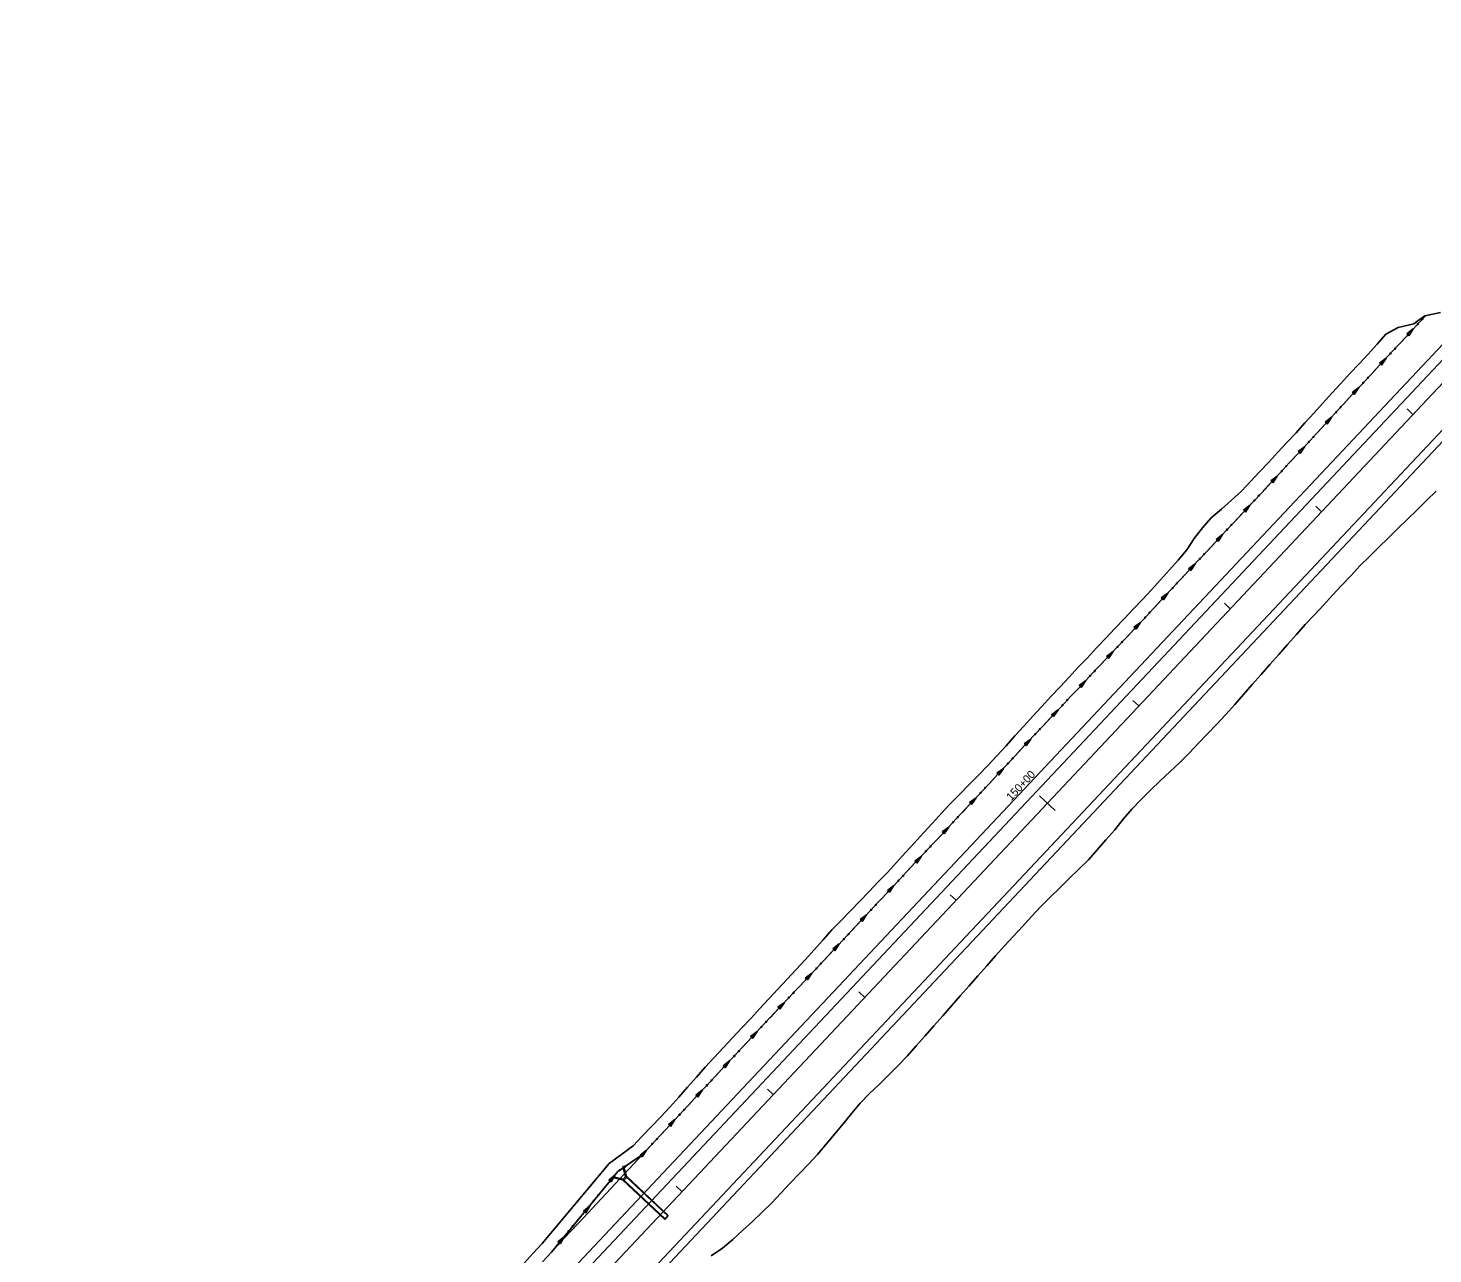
# Model space of a CAD drawing. Extents: x 1375694 to 1433473, y 1931050 to 1967991.
# Drawn here: x 1378305 to 1379358, y 1934333 to 1935253 of the extents above; entities that cross this region are included whole.
import ezdxf

# ---------------------------------------------------------------- set-up
doc = ezdxf.new("R2010")
doc.units = 0
for name, color, linetype in [('62', 7, 'Continuous'), ('R_Drainage', 7, 'Continuous'), ('R_Horz Alg', 7, 'Continuous'), ('R_Horz Alg Annot', 7, 'Continuous'), ('R_Proposed Const Limits', 7, 'Continuous'), ('R_Proposed Road', 7, 'Continuous')]:
    doc.layers.add(name, color=color, linetype=linetype)

msp = doc.modelspace()

# ---------------------------------------------------------------- linework, layer by layer
at = {"layer": '62'}
for p, q in [((1379343.4, 1935027), (1379338.5, 1935023.3)), ((1379338.5, 1935023.3), (1379340.1, 1935021.9)), ((1379340.1, 1935021.9), (1379343.4, 1935027)), ((1379323, 1935005), (1379318.1, 1935001.3)), ((1379318.1, 1935001.3), (1379319.6, 1934999.8)), ((1379319.6, 1934999.8), (1379323, 1935005)), ((1379302.5, 1934983), (1379297.6, 1934979.3)), ((1379297.6, 1934979.3), (1379299.2, 1934977.9)), ((1379299.2, 1934977.9), (1379302.5, 1934983)), ((1379282.1, 1934960.9), (1379277.3, 1934957.2)), ((1379278.9, 1934955.7), (1379282.1, 1934960.9)), ((1379277.3, 1934957.2), (1379278.9, 1934955.7)), ((1379261.8, 1934938.7), (1379257, 1934935.1)), ((1379258.5, 1934933.6), (1379261.8, 1934938.7)), ((1379257, 1934935.1), (1379258.5, 1934933.6)), ((1379241.4, 1934916.7), (1379236.5, 1934913.1)), ((1379238.1, 1934911.6), (1379241.4, 1934916.7)), ((1379236.5, 1934913.1), (1379238.1, 1934911.6)), ((1379220.9, 1934894.8), (1379216, 1934891.1)), ((1379217.6, 1934889.7), (1379220.9, 1934894.8)), ((1379216, 1934891.1), (1379217.6, 1934889.7)), ((1379200.4, 1934872.8), (1379195.5, 1934869.2)), ((1379195.5, 1934869.2), (1379197.1, 1934867.7)), ((1379197.1, 1934867.7), (1379200.4, 1934872.8)), ((1379179.9, 1934850.9), (1379175, 1934847.2)), ((1379175, 1934847.2), (1379176.6, 1934845.8)), ((1379176.6, 1934845.8), (1379179.9, 1934850.9)), ((1379159.4, 1934828.9), (1379154.5, 1934825.3)), ((1379154.5, 1934825.3), (1379156.1, 1934823.8)), ((1379156.1, 1934823.8), (1379159.4, 1934828.9)), ((1379138.9, 1934807), (1379134, 1934803.3)), ((1379134, 1934803.3), (1379135.6, 1934801.9)), ((1379135.6, 1934801.9), (1379138.9, 1934807)), ((1379118.3, 1934785.1), (1379113.4, 1934781.4)), ((1379113.4, 1934781.4), (1379115, 1934780)), ((1379115, 1934780), (1379118.3, 1934785.1)), ((1379097.7, 1934763.2), (1379092.8, 1934759.6)), ((1379092.8, 1934759.6), (1379094.4, 1934758.1)), ((1379094.4, 1934758.1), (1379097.7, 1934763.2)), ((1379077.1, 1934741.4), (1379072.2, 1934737.7)), ((1379072.2, 1934737.7), (1379073.7, 1934736.3)), ((1379073.7, 1934736.3), (1379077.1, 1934741.4)), ((1379056.6, 1934719.5), (1379051.7, 1934715.8)), ((1379051.7, 1934715.8), (1379053.2, 1934714.3)), ((1379053.2, 1934714.3), (1379056.6, 1934719.5)), ((1379036.1, 1934697.5), (1379031.2, 1934693.8)), ((1379032.8, 1934692.4), (1379036.1, 1934697.5)), ((1379031.2, 1934693.8), (1379032.8, 1934692.4)), ((1379015.6, 1934675.5), (1379010.7, 1934671.8)), ((1379012.3, 1934670.4), (1379015.6, 1934675.5)), ((1379010.7, 1934671.8), (1379012.3, 1934670.4)), ((1378995.1, 1934653.5), (1378990.2, 1934649.9)), ((1378991.8, 1934648.4), (1378995.1, 1934653.5)), ((1378990.2, 1934649.9), (1378991.8, 1934648.4)), ((1378974.6, 1934631.6), (1378969.7, 1934627.9)), ((1378971.3, 1934626.5), (1378974.6, 1934631.6)), ((1378969.7, 1934627.9), (1378971.3, 1934626.5)), ((1378954.1, 1934609.7), (1378949.2, 1934606)), ((1378949.2, 1934606), (1378950.7, 1934604.6)), ((1378950.7, 1934604.6), (1378954.1, 1934609.7)), ((1378933.6, 1934587.7), (1378928.7, 1934584.1)), ((1378928.7, 1934584.1), (1378930.2, 1934582.6)), ((1378930.2, 1934582.6), (1378933.6, 1934587.7)), ((1378913, 1934565.8), (1378908.2, 1934562.1)), ((1378908.2, 1934562.1), (1378909.7, 1934560.7)), ((1378909.7, 1934560.7), (1378913, 1934565.8)), ((1378892.5, 1934543.8), (1378887.6, 1934540.2)), ((1378887.6, 1934540.2), (1378889.2, 1934538.8)), ((1378889.2, 1934538.8), (1378892.5, 1934543.8)), ((1378871.9, 1934522), (1378867.1, 1934518.3)), ((1378867.1, 1934518.3), (1378868.6, 1934516.9)), ((1378868.6, 1934516.9), (1378871.9, 1934522)), ((1378851.4, 1934500.1), (1378846.5, 1934496.4)), ((1378846.5, 1934496.4), (1378848.1, 1934494.9)), ((1378848.1, 1934494.9), (1378851.4, 1934500.1)), ((1378830.9, 1934478.1), (1378826, 1934474.4)), ((1378826, 1934474.4), (1378827.6, 1934473)), ((1378827.6, 1934473), (1378830.9, 1934478.1)), ((1378810.4, 1934456.1), (1378805.5, 1934452.5)), ((1378805.5, 1934452.5), (1378807.1, 1934451)), ((1378807.1, 1934451), (1378810.4, 1934456.1)), ((1378789.9, 1934434.1), (1378785.1, 1934430.5)), ((1378786.6, 1934429), (1378789.9, 1934434.1)), ((1378785.1, 1934430.5), (1378786.6, 1934429)), ((1378768.5, 1934411.2), (1378763.7, 1934407.5)), ((1378765.2, 1934406.1), (1378768.5, 1934411.2)), ((1378763.7, 1934407.5), (1378765.2, 1934406.1)), ((1378745.1, 1934392.7), (1378740.4, 1934388.7)), ((1378742.1, 1934387.4), (1378745.1, 1934392.7)), ((1378740.4, 1934388.7), (1378742.1, 1934387.4)), ((1378726, 1934369.5), (1378721.3, 1934365.5)), ((1378723, 1934364.2), (1378726, 1934369.5)), ((1378721.3, 1934365.5), (1378723, 1934364.2)), ((1378706.9, 1934346.3), (1378702.2, 1934342.4)), ((1378702.2, 1934342.4), (1378703.9, 1934341)), ((1378703.9, 1934341), (1378706.9, 1934346.3))]:
    msp.add_line(p, q, dxfattribs=at)
for points in [[(1378690.5, 1934327.4), (1378697.3, 1934334.7), (1378704.1, 1934342.1), (1378710.9, 1934349.4), (1378717.8, 1934356.7), (1378724.6, 1934364), (1378731.4, 1934371.3), (1378738.2, 1934378.7), (1378745, 1934386), (1378751.8, 1934393.3), (1378758.7, 1934400.6), (1378765.5, 1934407.9), (1378772.3, 1934415.2), (1378779.1, 1934422.5), (1378786, 1934429.9), (1378792.8, 1934437.2), (1378799.6, 1934444.5), (1378806.4, 1934451.8), (1378813.2, 1934459.1), (1378820, 1934466.5), (1378826.8, 1934473.8), (1378833.7, 1934481.1), (1378840.5, 1934488.4), (1378847.3, 1934495.7), (1378854.1, 1934503), (1378861, 1934510.3), (1378867.8, 1934517.6), (1378874.7, 1934524.9), (1378881.5, 1934532.2), (1378888.4, 1934539.4), (1378895.2, 1934546.7), (1378902.1, 1934554), (1378908.9, 1934561.3), (1378915.7, 1934568.6), (1378922.5, 1934575.9), (1378929.4, 1934583.3), (1378936.2, 1934590.6), (1378943, 1934597.9), (1378949.9, 1934605.2), (1378956.7, 1934612.5), (1378963.5, 1934619.8), (1378970.3, 1934627.1), (1378977.2, 1934634.4), (1378984, 1934641.7), (1378990.9, 1934649), (1378997.7, 1934656.3), (1379004.5, 1934663.6), (1379011.3, 1934670.9), (1379018.1, 1934678.2), (1379025, 1934685.5), (1379031.8, 1934692.9), (1379038.6, 1934700.2), (1379045.4, 1934707.5), (1379052.2, 1934714.8), (1379059, 1934722.1), (1379065.9, 1934729.4), (1379072.7, 1934736.7), (1379079.6, 1934744), (1379086.4, 1934751.3), (1379093.3, 1934758.5), (1379100.2, 1934765.8), (1379107, 1934773.1), (1379113.9, 1934780.4), (1379120.7, 1934787.6), (1379127.6, 1934794.9), (1379134.4, 1934802.2), (1379141.3, 1934809.5), (1379148.1, 1934816.8), (1379154.9, 1934824.1), (1379161.7, 1934831.5), (1379168.6, 1934838.8), (1379175.4, 1934846.1), (1379182.2, 1934853.4), (1379189.1, 1934860.7), (1379195.9, 1934868), (1379202.7, 1934875.3), (1379209.5, 1934882.6), (1379216.4, 1934889.9), (1379223.2, 1934897.2), (1379230, 1934904.5), (1379236.8, 1934911.8), (1379243.6, 1934919.2), (1379250.4, 1934926.5), (1379257.3, 1934933.8), (1379264.1, 1934941.1), (1379270.8, 1934948.5), (1379277.6, 1934955.9), (1379284.3, 1934963.3), (1379291.1, 1934970.6), (1379297.8, 1934978), (1379304.7, 1934985.3), (1379311.5, 1934992.6), (1379318.3, 1935000), (1379325.1, 1935007.3), (1379331.9, 1935014.6), (1379338.7, 1935021.9), (1379345.5, 1935029.3), (1379348.9, 1935032.9), (1379352.3, 1935036.6)], [(1379333.2, 1935016), (1379338.7, 1935021.9), (1379343.4, 1935027)], [(1379333.2, 1935015.9), (1379333.2, 1935016)], [(1379312.7, 1934994), (1379318.3, 1935000), (1379323, 1935005)], [(1379312.7, 1934994), (1379312.7, 1934994)], [(1379292.3, 1934972), (1379297.8, 1934978), (1379302.5, 1934983)], [(1379292.3, 1934971.9), (1379292.3, 1934972)], [(1379272, 1934949.8), (1379277.6, 1934955.9), (1379282.1, 1934960.9)], [(1379272, 1934949.8), (1379272, 1934949.8)], [(1379251.6, 1934927.8), (1379257.3, 1934933.8), (1379261.8, 1934938.7)], [(1379251.6, 1934927.7), (1379251.6, 1934927.8)], [(1379231.2, 1934905.8), (1379236.8, 1934911.8), (1379241.4, 1934916.7)], [(1379231.2, 1934905.7), (1379231.2, 1934905.8)], [(1379210.7, 1934883.8), (1379216.4, 1934889.9), (1379220.9, 1934894.8)], [(1379210.6, 1934883.8), (1379210.7, 1934883.8)], [(1379190.2, 1934861.9), (1379195.9, 1934868), (1379200.4, 1934872.8)], [(1379190.1, 1934861.8), (1379190.2, 1934861.9)], [(1379169.6, 1934839.9), (1379175.4, 1934846.1), (1379179.9, 1934850.9)], [(1379169.6, 1934839.9), (1379169.6, 1934839.9)], [(1379149.1, 1934818), (1379154.9, 1934824.1), (1379159.4, 1934828.9)], [(1379149.1, 1934817.9), (1379149.1, 1934818)], [(1379128.6, 1934796), (1379134.4, 1934802.2), (1379138.9, 1934807)], [(1379128.6, 1934796), (1379128.6, 1934796)], [(1379108, 1934774.2), (1379113.9, 1934780.4), (1379118.3, 1934785.1)], [(1379108, 1934774.1), (1379108, 1934774.2)], [(1379087.4, 1934752.3), (1379093.3, 1934758.5), (1379097.7, 1934763.2)], [(1379087.4, 1934752.3), (1379087.4, 1934752.3)], [(1379066.8, 1934730.5), (1379072.7, 1934736.7), (1379077.1, 1934741.4)], [(1379066.8, 1934730.4), (1379066.8, 1934730.5)], [(1379046.3, 1934708.5), (1379052.2, 1934714.8), (1379056.6, 1934719.5)], [(1379046.3, 1934708.4), (1379046.3, 1934708.5)], [(1379025.9, 1934686.5), (1379031.8, 1934692.9), (1379036.1, 1934697.5)], [(1379025.8, 1934686.5), (1379025.9, 1934686.5)], [(1379005.4, 1934664.5), (1379011.3, 1934670.9), (1379015.6, 1934675.5)], [(1379005.4, 1934664.5), (1379005.4, 1934664.5)], [(1378984.9, 1934642.6), (1378990.9, 1934649), (1378995.1, 1934653.5)], [(1378984.8, 1934642.6), (1378984.9, 1934642.6)], [(1378964.3, 1934620.7), (1378970.3, 1934627.1), (1378974.6, 1934631.6)], [(1378964.3, 1934620.6), (1378964.3, 1934620.7)], [(1378943.8, 1934598.7), (1378949.9, 1934605.2), (1378954.1, 1934609.7)], [(1378943.8, 1934598.7), (1378943.8, 1934598.7)], [(1378923.3, 1934576.8), (1378929.4, 1934583.3), (1378933.6, 1934587.7)], [(1378923.3, 1934576.7), (1378923.3, 1934576.8)], [(1378902.8, 1934554.8), (1378908.9, 1934561.3), (1378913, 1934565.8)], [(1378902.8, 1934554.8), (1378902.8, 1934554.8)], [(1378882.2, 1934532.9), (1378888.4, 1934539.4), (1378892.5, 1934543.8)], [(1378882.2, 1934532.9), (1378882.2, 1934532.9)], [(1378861.7, 1934511), (1378867.8, 1934517.6), (1378871.9, 1934522)], [(1378861.6, 1934511), (1378861.7, 1934511)], [(1378841.2, 1934489.1), (1378847.3, 1934495.7), (1378851.4, 1934500.1)], [(1378841.1, 1934489.1), (1378841.2, 1934489.1)], [(1378820.7, 1934467.1), (1378826.8, 1934473.8), (1378830.9, 1934478.1)], [(1378820.6, 1934467.1), (1378820.7, 1934467.1)], [(1378800.2, 1934445.1), (1378806.4, 1934451.8), (1378810.4, 1934456.1)], [(1378800.2, 1934445.1), (1378800.2, 1934445.1)], [(1378779.7, 1934423.2), (1378786, 1934429.9), (1378789.9, 1934434.1)], [(1378779.7, 1934423.1), (1378779.7, 1934423.2)], [(1378756.8, 1934401.9), (1378765.5, 1934407.9), (1378768.5, 1934411.2)], [(1378735.5, 1934381.1), (1378745.1, 1934392.7)], [(1378735.5, 1934381.1), (1378735.5, 1934381.1)], [(1378716.4, 1934357.9), (1378726, 1934369.5)], [(1378716.4, 1934357.9), (1378716.4, 1934357.9)], [(1378697.3, 1934334.7), (1378706.9, 1934346.3)], [(1378697.8, 1934335.2), (1378697.8, 1934335.3)]]:
    msp.add_lwpolyline(points, dxfattribs=at)
for centre in [(1379350.2, 1935034.4), (1379346.8, 1935030.7), (1379329.8, 1935012.3), (1379326.3, 1935008.6), (1379309.3, 1934990.3), (1379305.9, 1934986.7), (1379288.9, 1934968.3), (1379285.5, 1934964.6), (1379265.2, 1934942.4), (1379268.6, 1934946.1), (1379244.8, 1934920.4), (1379248.2, 1934924.1), (1379224.3, 1934898.4), (1379227.7, 1934902.1), (1379203.8, 1934876.5), (1379207.2, 1934880.2), (1379183.3, 1934854.6), (1379186.7, 1934858.2), (1379162.8, 1934832.6), (1379166.2, 1934836.3), (1379142.3, 1934810.6), (1379145.7, 1934814.3), (1379125.2, 1934792.4), (1379121.7, 1934788.7), (1379104.6, 1934770.5), (1379101.1, 1934766.9), (1379083.9, 1934748.7), (1379080.5, 1934745), (1379063.4, 1934726.8), (1379059.9, 1934723.1), (1379042.9, 1934704.8), (1379039.5, 1934701.2), (1379019, 1934679.2), (1379022.4, 1934682.8), (1378998.5, 1934657.2), (1379001.9, 1934660.9), (1378978, 1934635.3), (1378981.4, 1934638.9), (1378957.5, 1934613.4), (1378960.9, 1934617), (1378936.9, 1934591.4), (1378940.4, 1934595.1), (1378916.4, 1934569.5), (1378919.9, 1934573.1), (1378895.9, 1934547.5), (1378899.3, 1934551.2), (1378878.8, 1934529.3), (1378875.3, 1934525.6), (1378858.2, 1934507.4), (1378854.8, 1934503.7), (1378837.7, 1934485.4), (1378834.3, 1934481.8), (1378817.2, 1934463.5), (1378813.8, 1934459.8), (1378796.7, 1934441.5), (1378793.3, 1934437.8), (1378772.8, 1934415.9), (1378776.3, 1934419.5), (1378748.6, 1934396.2), (1378752.7, 1934399), (1378729.1, 1934373.4), (1378732.3, 1934377.2), (1378710, 1934350.2), (1378713.2, 1934354.1)]:
    msp.add_circle(centre, 0.375, dxfattribs=at)
at = {"layer": 'R_Drainage'}
for p, q in [((1378743.3, 1934390.7), (1378743.4, 1934391.2)), ((1378743.3, 1934390.7), (1378750.6, 1934389)), ((1378743.4, 1934391.2), (1378750.8, 1934389.4)), ((1378750.7, 1934398.9), (1378751.2, 1934399.1)), ((1378750.7, 1934398.9), (1378752.9, 1934391.6)), ((1378750.8, 1934389.4), (1378782.5, 1934359.6)), ((1378751.2, 1934399.1), (1378753.3, 1934391.9)), ((1378752.9, 1934391.6), (1378784.5, 1934361.9)), ((1378753.3, 1934391.9), (1378784.9, 1934362.2)), ((1378750.6, 1934389), (1378782.2, 1934359.3)), ((1378784.9, 1934362.2), (1378782.2, 1934359.2))]:
    msp.add_line(p, q, dxfattribs=at)
for points in [[(1378750.6, 1934389), (1378753.3, 1934391.9)], [(1378751.3, 1934388.3), (1378754.1, 1934391.2)]]:
    msp.add_lwpolyline(points, dxfattribs=at)
at = {"layer": 'R_Horz Alg'}
msp.add_line((1377884.3, 1933411.6), (1379607.9, 1935244.4), dxfattribs=at)
at = {"layer": 'R_Horz Alg Annot'}
for points in [[(1379338.8, 1934967), (1379343.1, 1934962.9)], [(1379270.3, 1934894.1), (1379274.6, 1934890)], [(1379201.8, 1934821.3), (1379206.1, 1934817.2)], [(1379133.2, 1934748.4), (1379137.6, 1934744.3)], [(1379063.3, 1934677), (1379074.9, 1934666)], [(1378996.2, 1934602.7), (1379000.6, 1934598.6)], [(1378927.7, 1934529.9), (1378932.1, 1934525.8)], [(1378859.2, 1934457), (1378863.6, 1934452.9)], [(1378790.7, 1934384.2), (1378795.1, 1934380.1)]]:
    msp.add_lwpolyline(points, dxfattribs=at)
at = {"layer": 'R_Proposed Const Limits'}
for points in [[(1378676.9, 1934326.5), (1378683.6, 1934334), (1378690.3, 1934341.3), (1378740.6, 1934401.1), (1378758.5, 1934414.5), (1378765.4, 1934421.7), (1378772.3, 1934428.9), (1378779.2, 1934436.2), (1378786.1, 1934443.4), (1378792.7, 1934450.9), (1378799.4, 1934458.4), (1378806, 1934465.9), (1378812.6, 1934473.4), (1378819.4, 1934480.7), (1378826.2, 1934488.1), (1378833.1, 1934495.4), (1378839.9, 1934502.7), (1378846.7, 1934510), (1378853.5, 1934517.3), (1378860.3, 1934524.6), (1378867.1, 1934531.9), (1378874, 1934539.3), (1378880.8, 1934546.6), (1378887.5, 1934554), (1378894.2, 1934561.4), (1378900.9, 1934568.9), (1378907.5, 1934576.3), (1378914.5, 1934583.5), (1378921.4, 1934590.7), (1378928.4, 1934597.9), (1378935.4, 1934605.1), (1378942.3, 1934612.3), (1378949.2, 1934619.5), (1378955.9, 1934626.9), (1378962.7, 1934634.3), (1378969.4, 1934641.7), (1378976.1, 1934649.1), (1378982.9, 1934656.5), (1378989.6, 1934663.9), (1378996.5, 1934671.1), (1379003.5, 1934678.2), (1379010.5, 1934685.4), (1379017.5, 1934692.5), (1379024.5, 1934699.7), (1379031.3, 1934707), (1379038.1, 1934714.4), (1379044.8, 1934721.8), (1379051.5, 1934729.2), (1379058.3, 1934736.6), (1379065, 1934743.9), (1379071.8, 1934751.3), (1379078.6, 1934758.6), (1379085.4, 1934766), (1379092.2, 1934773.3), (1379099.1, 1934780.5), (1379106, 1934787.8), (1379112.8, 1934795.1), (1379119.7, 1934802.3), (1379126.6, 1934809.6), (1379133.4, 1934816.9), (1379140.3, 1934824.2), (1379147.1, 1934831.5), (1379153.9, 1934838.8), (1379160.6, 1934846.3), (1379167.2, 1934853.7), (1379173.6, 1934861.5), (1379179.1, 1934870), (1379185.3, 1934878), (1379191.9, 1934885.5), (1379199.5, 1934892), (1379207.1, 1934898.6), (1379214.6, 1934905.3), (1379221.4, 1934912.6), (1379228.2, 1934919.9), (1379235.1, 1934927.2), (1379241.9, 1934934.6), (1379248.6, 1934941.9), (1379255.5, 1934949.2), (1379262.2, 1934956.6), (1379269, 1934964), (1379275.7, 1934971.4), (1379282.4, 1934978.8), (1379289.2, 1934986.2), (1379295.9, 1934993.5), (1379302.7, 1935000.9), (1379309.5, 1935008.2), (1379316.2, 1935015.6), (1379322.9, 1935023), (1379332.1, 1935028.2), (1379343.8, 1935030.9), (1379347.8, 1935033.9), (1379352, 1935036.9), (1379363.9, 1935039.4)], [(1378817.1, 1934332), (1378825.6, 1934337.7), (1378833.4, 1934344.1), (1378840.6, 1934351), (1378848, 1934357.7), (1378855.2, 1934364.7), (1378862.4, 1934371.7), (1378869.2, 1934379), (1378876.1, 1934386.2), (1378883, 1934393.5), (1378889.9, 1934400.7), (1378896.7, 1934408), (1378903.3, 1934415.6), (1378909.7, 1934423.3), (1378916.1, 1934431), (1378922.4, 1934438.8), (1378928.8, 1934446.5), (1378935.8, 1934453.7), (1378943.1, 1934460.5), (1378950.2, 1934467.6), (1378957.2, 1934474.7), (1378964.2, 1934481.9), (1378970.8, 1934489.4), (1378977.4, 1934496.9), (1378984, 1934504.4), (1378990.6, 1934512), (1378997.2, 1934519.5), (1379003.8, 1934527), (1379010.4, 1934534.5), (1379017, 1934542), (1379023.7, 1934549.5), (1379030.3, 1934557), (1379037, 1934564.4), (1379043.8, 1934571.7), (1379050.6, 1934579.1), (1379057.3, 1934586.5), (1379064.1, 1934593.9), (1379071.1, 1934601), (1379078.3, 1934607.9), (1379085.5, 1934614.8), (1379092.6, 1934621.9), (1379099.8, 1934628.9), (1379106.4, 1934636.4), (1379113, 1934643.9), (1379119.6, 1934651.5), (1379125.8, 1934659.3), (1379132.4, 1934666.9), (1379139.3, 1934674.1), (1379146.4, 1934681.1), (1379153.6, 1934688.1), (1379160.9, 1934694.9), (1379168.3, 1934701.8), (1379175.4, 1934708.8), (1379182.2, 1934716.1), (1379189.2, 1934723.3), (1379196, 1934730.6), (1379202.9, 1934737.8), (1379209.6, 1934745.3), (1379216.1, 1934752.8), (1379222.7, 1934760.4), (1379229.3, 1934767.9), (1379235.9, 1934775.5), (1379242.5, 1934783), (1379249.1, 1934790.5), (1379255.8, 1934797.9), (1379262.4, 1934805.4), (1379269.3, 1934812.7), (1379276.1, 1934820), (1379282.9, 1934827.3), (1379289.7, 1934834.7), (1379296.5, 1934842), (1379303.4, 1934849.3), (1379310.5, 1934856.3), (1379317.6, 1934863.3), (1379324.7, 1934870.4), (1379331.9, 1934877.4), (1379339, 1934884.4), (1379346.2, 1934891.4), (1379353.4, 1934898.3), (1379360.6, 1934905.3)]]:
    msp.add_lwpolyline(points, dxfattribs=at)
at = {"layer": 'R_Proposed Road'}
for p, q in [((1377869.7, 1933425.3), (1379593.4, 1935258.1)), ((1377875.5, 1933419.8), (1379599.2, 1935252.6)), ((1377901.7, 1933395.1), (1379625.4, 1935228)), ((1377906.1, 1933391), (1379629.8, 1935223.9))]:
    msp.add_line(p, q, dxfattribs=at)
for points in [[(1378697.3, 1934334.7), (1378747, 1934395.1), (1378765.5, 1934407.9), (1378771.1, 1934413.9)], [(1378756.8, 1934401.9), (1378756.8, 1934401.9)]]:
    msp.add_lwpolyline(points, dxfattribs=at)

# ---------------------------------------------------------------- texts
at = {"layer": 'R_Horz Alg Annot'}
msp.add_text('150+00', height=6, rotation=46.7586, dxfattribs=at).set_placement((1379042, 1934672.8))

doc.saveas('drawing.dxf')
